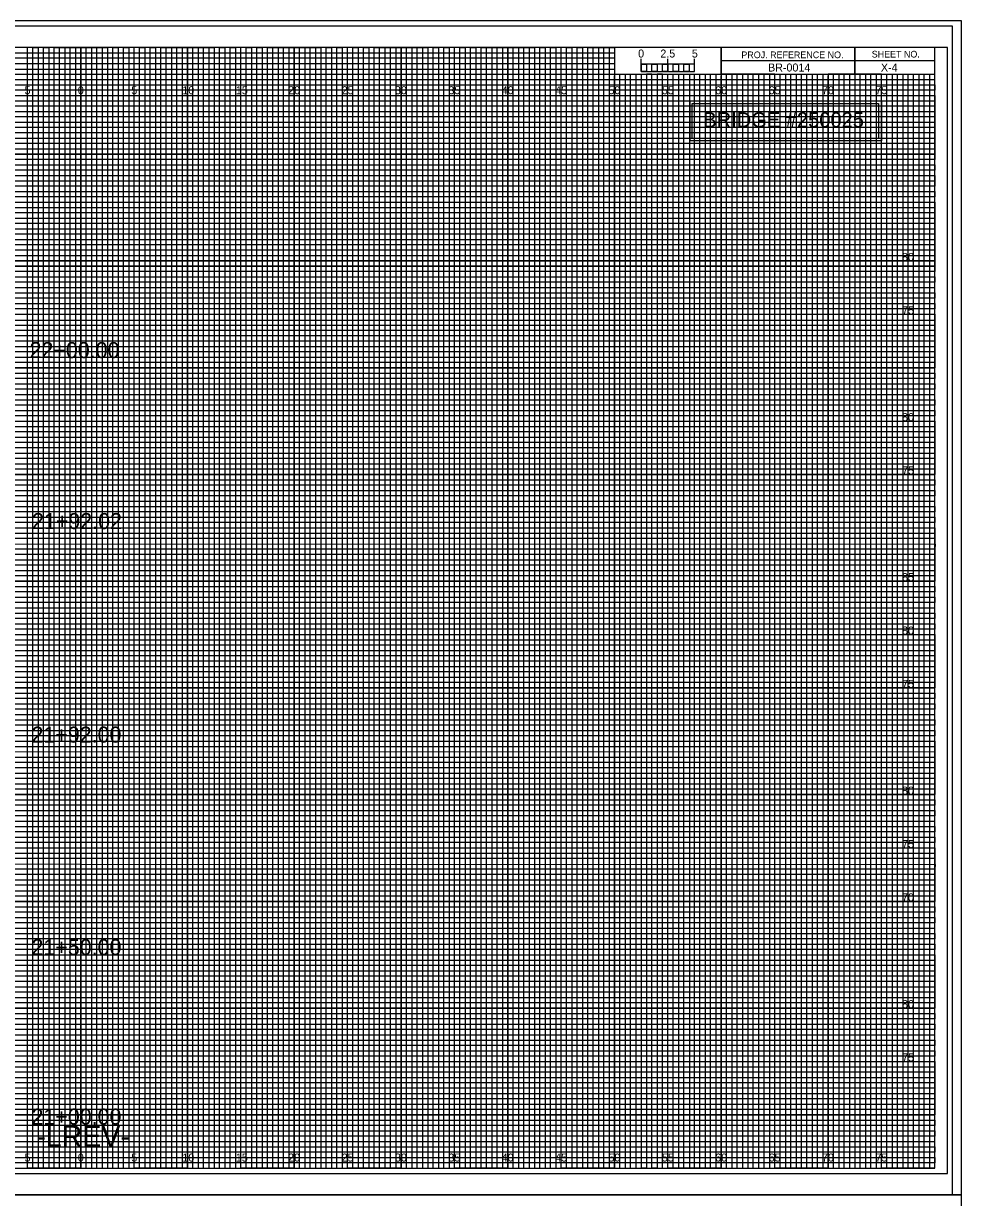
# Model space of a CAD drawing. Extents: x -8 to 533, y -20 to 768.
# Drawn here: x 74.6 to 162.5, y 327.2 to 437.2 of the extents above; entities that cross this region are included whole.
import ezdxf

# ---------------------------------------------------------------- set-up
doc = ezdxf.new("R2010")
doc.units = 0
for name, color, linetype in [('Old_Level_1', 7, 'Continuous'), ('Old_Level_34', 7, 'Continuous'), ('Prop Grid Mask', 7, 'Continuous'), ('Prop XS Alignment Label', 7, 'Continuous'), ('Prop XS Bar Scale Labels', 7, 'Continuous'), ('Prop XS Elevation Labels', 7, 'Continuous'), ('Prop XS Offset Labels', 7, 'Continuous'), ('Prop XS Project Number', 7, 'Continuous'), ('Prop XS Sheet Number', 7, 'Continuous'), ('Prop XS Station Labels', 7, 'Continuous'), ('Sheet Cross Section CELL', 7, 'Continuous'), ('Sheet Cross Section Grid Major CELL', 7, 'Continuous'), ('Sheet Cross Section Grid Middle CELL', 7, 'Continuous'), ('Sheet Cross Section Grid Minor 1 CELL', 7, 'Continuous'), ('Sheet Cross Section Grid Minor 2 CELL', 7, 'Continuous'), ('Sheet Cross Section Scale CELL', 7, 'Continuous'), ('Sheet Cutting Line CELL', 7, 'Continuous'), ('Sheet DOT Grid CELL', 7, 'Continuous'), ('Sheet Plot Border Inside CELL', 7, 'Continuous'), ('Sheet Plot Border Outside CELL', 7, 'Continuous'), ('WEI Plot Border', 7, 'Continuous')]:
    doc.layers.add(name, color=color, linetype=linetype)

msp = doc.modelspace()

# ---------------------------------------------------------------- linework, layer by layer
at = {"layer": 'Old_Level_34'}
msp.add_lwpolyline([(137.26, 429.75), (154.74, 429.75), (154.74, 426.46), (137.26, 426.46)], close=True, dxfattribs=at)
at = {"layer": 'Prop Grid Mask'}
msp.add_lwpolyline([(137.08, 430), (155, 430), (155, 426.24), (137.08, 426.24)], close=True, dxfattribs=at)
at = {"layer": 'Sheet Cross Section CELL'}
for p, q in [((152.5, 435), (152.5, 432.5)), ((152.5, 432.5), (152.5, 435)), ((160, 433.75), (140, 433.75)), ((140, 433.75), (140, 432.5)), ((140, 432.5), (160, 432.5))]:
    msp.add_line(p, q, dxfattribs=at)
for points in [[(160, 435), (0, 435), (0, 330), (160, 330)], [(140, 435), (130, 435), (130, 432.51), (140, 432.51)], [(160, 435), (140, 435), (140, 432.5), (160, 432.5)]]:
    msp.add_lwpolyline(points, close=True, dxfattribs=at)
at = {"layer": 'Sheet Cross Section Grid Major CELL'}
for p, q in [((75, 435), (70, 435)), ((75, 330), (75, 435)), ((85, 435), (80, 435)), ((80, 435), (80, 330)), ((85, 330), (85, 435)), ((95, 435), (90, 435)), ((90, 435), (90, 330)), ((95, 330), (95, 435)), ((105, 435), (100, 435)), ((100, 435), (100, 330)), ((105, 330), (105, 435)), ((115, 435), (110, 435)), ((110, 435), (110, 330)), ((115, 330), (115, 435)), ((125, 435), (120, 435)), ((120, 435), (120, 330)), ((125, 330), (125, 435)), ((130, 435), (130, 330)), ((135, 330), (135, 432.5)), ((145, 432.5), (140, 432.5)), ((140, 432.5), (140, 330)), ((145, 330), (145, 432.5)), ((155, 432.5), (150, 432.5)), ((150, 432.5), (150, 330)), ((155, 330), (155, 432.5)), ((80, 330), (75, 330)), ((90, 330), (85, 330)), ((100, 330), (95, 330)), ((110, 330), (105, 330)), ((120, 330), (115, 330)), ((130, 330), (125, 330)), ((140, 330), (135, 330)), ((150, 330), (145, 330)), ((160, 330), (155, 330)), ((160, 330), (160, 330))]:
    msp.add_line(p, q, dxfattribs=at)
for points in [[(0, 430), (160, 430), (160, 425), (0, 425)], [(0, 420), (160, 420), (160, 415), (0, 415)], [(0, 410), (160, 410), (160, 405), (0, 405)], [(0, 400), (160, 400), (160, 395), (0, 395)], [(0, 390), (160, 390), (160, 385), (0, 385)], [(0, 380), (160, 380), (160, 375), (0, 375)], [(0, 370), (160, 370), (160, 365), (0, 365)], [(0, 360), (160, 360), (160, 355), (0, 355)], [(0, 350), (160, 350), (160, 345), (0, 345)], [(0, 340), (160, 340), (160, 335), (0, 335)]]:
    msp.add_lwpolyline(points, dxfattribs=at)
at = {"layer": 'Sheet Cross Section Grid Middle CELL'}
for points in [[(72.5, 330), (77.5, 330), (77.5, 435), (82.5, 435), (82.5, 330), (87.5, 330), (87.5, 435), (92.5, 435), (92.5, 330), (97.5, 330), (97.5, 435), (102.5, 435), (102.5, 330), (107.5, 330), (107.5, 435), (112.5, 435), (112.5, 330), (117.5, 330), (117.5, 435), (122.5, 435), (122.5, 330), (127.5, 330), (127.5, 435), (129.97, 435), (130, 435), (130, 432.5), (132.5, 432.5), (132.5, 330), (137.5, 330), (137.5, 432.5), (142.5, 432.5), (142.5, 330), (147.5, 330), (147.5, 432.5), (152.5, 432.5), (152.5, 330), (157.5, 330), (157.5, 432.5)], [(0, 432.5), (137.5, 432.5)], [(0, 422.5), (160, 422.5), (160, 427.5), (0, 427.5)], [(0, 412.5), (160, 412.5), (160, 417.5), (0, 417.5)], [(0, 402.5), (160, 402.5), (160, 407.5), (0, 407.5)], [(0, 392.5), (160, 392.5), (160, 397.5), (0, 397.5)], [(0, 382.5), (160, 382.5), (160, 387.5), (0, 387.5)], [(0, 372.5), (160, 372.5), (160, 377.5), (0, 377.5)], [(0, 362.5), (160, 362.5), (160, 367.5), (0, 367.5)], [(0, 352.5), (160, 352.5), (160, 357.5), (0, 357.5)], [(0, 342.5), (160, 342.5), (160, 347.5), (0, 347.5)], [(0, 332.5), (160, 332.5), (160, 337.5), (0, 337.5)]]:
    msp.add_lwpolyline(points, dxfattribs=at)
at = {"layer": 'Sheet Cross Section Grid Minor 1 CELL'}
for p, q in [((0, 434.5), (130, 434.5)), ((130, 433.99), (0, 433.99)), ((0, 433.5), (130, 433.5)), ((130, 434.5), (130, 433.99)), ((130, 433.5), (130, 432.94)), ((130, 432.94), (0, 432.94)), ((0, 432), (160, 432))]:
    msp.add_line(p, q, dxfattribs=at)
for points in [[(0, 431.5), (135, 431.5), (160, 431.5), (160, 431), (0, 431)], [(0, 430.5), (160, 430.5), (160, 429.5), (0, 429.5)], [(0, 429), (160, 429), (160, 428.5), (0, 428.49)], [(0, 428), (160, 428), (160, 427), (0, 427)], [(0, 426.5), (160, 426.5), (160, 426), (0, 426)], [(0, 425.5), (160, 425.5), (160, 424.5), (0, 424.5)], [(0, 424), (160, 424), (160, 423.5), (0, 423.5)], [(0, 423), (160, 423), (160, 422), (0, 422)], [(0, 421.5), (160, 421.5), (160, 421), (0, 421)], [(0, 420.5), (160, 420.5), (160, 419.5), (0, 419.5)], [(0, 419), (160, 419), (160, 418.5), (0, 418.5)], [(0, 418), (160, 418), (160, 416.98), (160, 416.5), (160, 416), (0, 416)], [(0, 417), (160, 417), (160, 416.5), (0, 416.5)], [(0, 415.5), (160, 415.5), (160, 414.5), (0, 414.51)], [(0, 414.51), (160, 414.5), (160, 414), (0, 414)], [(0, 413.5), (160, 413.5), (160, 413), (0, 413)], [(0, 412), (160, 412), (160, 411.5), (0, 411.5)], [(0, 411), (160, 411), (160, 410.5), (0, 410.5)], [(-0.04, 409.44), (160, 409.44), (160, 408.94), (-0.04, 408.94)], [(0, 408.5), (160, 408.5), (160, 408), (0, 408)], [(0, 407), (160, 407), (160, 406.5), (0, 406.5)], [(0, 406), (160, 406), (160, 405.5), (0, 405.5)], [(0, 404.5), (160, 404.5), (160, 404), (0, 404)], [(0, 403.5), (160, 403.5), (160, 403), (0, 403)], [(0, 402), (160, 402), (160, 401.5), (0, 401.5)], [(0, 401), (160, 401), (160, 400.5), (0, 400.5)], [(0, 399.5), (160, 399.5), (160, 398.99), (0, 399)], [(0, 398.5), (160, 398.5), (160, 398), (0, 398)], [(0, 397), (160, 397), (160, 396.5), (0, 396.5)], [(0, 396), (160, 396), (160, 395.5), (0, 395.5)], [(0, 394.5), (160, 394.5), (160, 394), (0, 394)], [(0, 393.5), (160, 393.5), (160, 393), (0, 393)], [(0, 392), (160, 392), (160, 391.5), (0, 391.5)], [(0, 391), (160, 391), (160, 390.5), (0, 390.5)], [(0, 389.5), (160, 389.5), (160, 389), (0, 389)], [(0, 388.5), (160.03, 388.45), (160, 388), (0, 388)], [(0, 387), (160, 387), (160, 386.5), (0, 386.5)], [(0, 386), (160, 386), (160, 385.5), (0, 385.5)], [(0, 384.5), (160, 384.5), (160, 384), (0, 384)], [(0, 383.5), (160, 383.5), (160, 383), (0, 383)], [(0, 382), (160, 382), (160, 381.5), (0, 381.5)], [(0, 381), (160, 381), (160, 380.5), (0, 380.5)], [(0, 379.5), (160, 379.5), (160, 379), (0, 379)], [(0, 378.5), (160, 378.5), (160, 378), (0, 378)], [(0, 377), (160, 377), (160, 376.5), (0, 376.5)], [(0, 376), (160, 376), (160, 375.5), (0, 375.5)], [(0, 374.5), (160, 374.5), (160, 374), (0, 374)], [(0, 373.5), (160, 373.5), (160, 373), (0, 373)], [(0, 372), (160, 372), (160, 371.5), (0, 371.5)], [(0, 371), (160, 371), (160, 370.5), (0, 370.5)], [(0, 369.5), (160, 369.5), (160, 368.99), (0, 369)], [(0, 368.5), (160, 368.5), (160, 368), (0, 368)], [(0, 367), (160, 367), (160, 366.5), (0, 366.5)], [(0, 366), (160, 366), (160, 365.5), (0, 365.5)], [(0, 364.5), (160, 364.5), (160, 364), (0, 364)], [(0, 363.5), (160, 363.5), (160, 363), (0, 363)], [(0, 362), (160, 362), (160, 361.5), (0, 361.5)], [(0, 361), (160, 361), (160, 360.5), (0, 360.5)], [(0, 359.5), (160, 359.5), (160, 359), (0, 359)], [(0, 358.5), (160.03, 358.45), (160, 358), (0, 358)], [(0, 357), (160, 357), (160, 356.5), (0, 356.5)], [(0, 356), (160, 356), (160, 355.5), (0, 355.5)], [(0, 354.5), (160, 354.5), (160, 354), (0, 354)], [(0, 353.5), (160, 353.5), (160, 353), (0, 353)], [(0, 352), (160, 352), (160, 351.5), (0, 351.5)], [(0, 351), (160, 351), (160, 350.5), (0, 350.5)], [(0, 349.5), (160, 349.5), (160, 349), (0, 349)], [(0, 348.5), (160, 348.5), (160, 348), (0, 348)], [(0, 347), (160, 347), (160, 346.5), (0, 346.5)], [(0, 346), (160, 346), (160, 345.5), (0, 345.5)], [(0, 344.5), (160, 344.5), (160, 344), (0, 344)], [(0, 343.5), (160, 343.5), (160, 343), (0, 343)], [(0, 342), (160, 342), (160, 341.5), (0, 341.5)], [(0, 341), (160, 341), (160, 340.5), (0, 340.5)], [(0, 339.5), (160, 339.5), (160, 339), (0, 339)], [(0, 338.5), (160, 338.5), (160, 338), (0, 338)], [(0, 337), (160, 337), (160, 336.5), (0, 336.5)], [(0, 336), (160, 336), (160, 335.5), (0, 335.5)], [(0, 334.5), (160, 334.5), (160, 334), (0, 334)], [(0, 333.5), (160, 333.5), (160, 333), (0, 333)], [(0, 332), (160, 332), (160, 331.5), (0, 331.5)], [(0, 331), (160, 331), (160, 330.5), (0, 330.5)]]:
    msp.add_lwpolyline(points, dxfattribs=at)
at = {"layer": 'Sheet Cross Section Grid Minor 2 CELL'}
for p, q in [((133.5, 432.5), (133, 432.5)), ((133, 432.5), (133, 330)), ((133.5, 330), (133.5, 432.5)), ((134.5, 432.5), (134, 432.5)), ((134, 432.5), (134, 330)), ((134.5, 330), (134.5, 432.5)), ((133, 330), (132.5, 330)), ((134, 330), (133.5, 330))]:
    msp.add_line(p, q, dxfattribs=at)
for points in [[(75, 330), (75.5, 330), (75.5, 435), (76, 435), (76, 330)], [(76, 330), (76.5, 330), (76.5, 435), (77, 435), (77, 330)], [(77.5, 330), (78, 330), (78, 435), (78.5, 435), (78.5, 330)], [(78.5, 330), (79, 330), (79, 435), (79.5, 435), (79.5, 330)], [(80, 330), (80.5, 330), (80.5, 435), (81, 435), (81, 330)], [(81, 330), (81.5, 330), (81.5, 435), (82, 435), (82, 330)], [(82.5, 330), (83, 330), (83, 435), (83.5, 435), (83.5, 330)], [(83.5, 330), (84, 330), (84, 435), (84.5, 435), (84.5, 330)], [(85, 330), (85.5, 330), (85.5, 435), (86, 435), (86, 330)], [(86, 330), (86.5, 330), (86.5, 435), (87, 435), (87, 330)], [(87.5, 330), (88, 330), (88, 435), (88.5, 435), (88.5, 330)], [(88.5, 330), (89, 330), (89, 435), (89.5, 435), (89.5, 330)], [(90, 330), (90.5, 330), (90.5, 435), (91, 435), (91, 330)], [(91, 330), (91.5, 330), (91.5, 435), (92, 435), (92, 330)], [(92.5, 330), (93, 330), (93, 435), (93.5, 435), (93.5, 330)], [(93.5, 330), (94, 330), (94, 435), (94.5, 435), (94.5, 330)], [(95, 330), (95.5, 330), (95.5, 435), (96, 435), (96, 330)], [(96, 330), (96.5, 330), (96.5, 435), (97, 435), (97, 330)], [(97.5, 330), (98, 330), (98, 435), (98.5, 435), (98.5, 330)], [(98.5, 330), (99, 330), (99, 435), (99.5, 435), (99.5, 330)], [(100, 330), (100.5, 330), (100.5, 435), (101, 435), (101, 330)], [(101, 330), (101.5, 330), (101.5, 435), (102, 435), (102, 330)], [(102.5, 330), (103, 330), (103, 435), (103.5, 435), (103.5, 330)], [(103.5, 330), (104, 330), (104, 435), (104.5, 435), (104.5, 330)], [(105, 330), (105.5, 330), (105.5, 435), (106, 435), (106, 330)], [(106, 330), (106.5, 330), (106.5, 435), (107, 435), (107, 330)], [(107.5, 330), (108, 330), (108, 435), (108.5, 435), (108.5, 330)], [(108.5, 330), (109, 330), (109, 435), (109.5, 435), (109.5, 330)], [(110, 330), (110.5, 330), (110.5, 435), (111, 435), (111, 330)], [(111, 330), (111.5, 330), (111.5, 435), (112, 435), (112, 330)], [(112.5, 330), (113, 330), (113, 435), (113.5, 435), (113.5, 330)], [(113.5, 330), (114, 330), (114, 435), (114.5, 435), (114.5, 330)], [(115, 330), (115.5, 330), (115.5, 435), (116, 435), (116, 330)], [(116, 330), (116.5, 330), (116.5, 435), (117, 435), (117, 330)], [(117.5, 330), (118, 330), (118, 435), (118.5, 435), (118.5, 330)], [(118.5, 330), (119, 330), (119, 435), (119.5, 435), (119.5, 330)], [(120, 330), (120.5, 330), (120.5, 435), (121, 435), (121, 330)], [(121, 330), (121.5, 330), (121.5, 435), (122, 435), (122, 330)], [(122.5, 330), (123, 330), (123, 435), (123.5, 435), (123.5, 330)], [(123.5, 330), (124, 330), (124, 435), (124.5, 435), (124.5, 330)], [(125, 330), (125.5, 330), (125.5, 435), (126, 435), (126, 330)], [(126, 330), (126.5, 330), (126.5, 435), (127, 435), (127, 330)], [(127.5, 330), (128, 330), (128, 435), (128.5, 435), (128.5, 330)], [(128.5, 330), (129, 330), (129, 435), (129.5, 435), (129.5, 330)], [(130, 330), (130.5, 330), (130.5, 432.5), (131.01, 432.5), (131.01, 330)], [(131, 330), (131.5, 330), (131.5, 432.5), (132, 432.5), (132, 330)], [(135, 330), (135.49, 330), (135.49, 432.5), (136, 432.5), (136, 330)], [(136, 330), (136.5, 330), (136.5, 432.5), (137.03, 432.5), (137.03, 330)], [(137.5, 330), (138, 330), (138, 432.5), (138.5, 432.5), (138.5, 330)], [(138.5, 330), (139, 330), (139, 432.5), (139.5, 432.5), (139.5, 330)], [(140, 330), (140.5, 330), (140.5, 432.5), (141, 432.5), (141, 330)], [(141, 330), (141.5, 330), (141.5, 432.5), (142, 432.5), (142, 330)], [(142.5, 330), (143, 330), (143, 432.5), (143.5, 432.5), (143.5, 330)], [(143.5, 330), (144, 330), (144, 432.5), (144.5, 432.5), (144.5, 330)], [(145, 330), (145.5, 330), (145.5, 432.5), (146, 432.5), (146, 330)], [(146, 330), (146.5, 330), (146.5, 432.5), (147, 432.5), (147, 330)], [(147.5, 330), (148, 330), (148, 432.5), (148.5, 432.5), (148.5, 330)], [(148.5, 330), (149, 330), (149, 432.5), (149.5, 432.5), (149.5, 330)], [(150, 330), (150.5, 330), (150.5, 432.5), (151, 432.5), (151, 330)], [(151, 330), (151.5, 330), (151.5, 432.5), (152, 432.5), (152, 330)], [(152.5, 330), (153, 330), (153, 432.5), (153.5, 432.5), (153.5, 330)], [(153.5, 330), (154, 330), (154, 432.5), (154.5, 432.5), (154.5, 330)], [(155, 330), (155.5, 330), (155.5, 432.5), (156, 432.5), (156, 330)], [(156, 330), (156.5, 330), (156.5, 432.5), (157, 432.5), (157, 330)], [(157.5, 330), (158, 330), (158, 432.5), (158.5, 432.5), (158.5, 330)], [(158.5, 330), (159, 330), (159, 432.5), (159.5, 432.5), (159.5, 330)]]:
    msp.add_lwpolyline(points, dxfattribs=at)
at = {"layer": 'Sheet Cross Section Scale CELL'}
for p, q in [((132.5, 432.75), (132.5, 433.95)), ((132.5, 433.45), (132.5, 433.95)), ((135, 432.75), (135, 433.95)), ((137.5, 432.75), (137.5, 433.95)), ((137.5, 433.45), (137.5, 433.95))]:
    msp.add_line(p, q, dxfattribs=at)
for points in [[(137.5, 433.45), (132.5, 433.45), (132.5, 432.75), (137.5, 432.75)], [(132.5, 433.45), (133, 433.45), (133, 432.75), (132.5, 432.75)], [(133.5, 433.45), (134, 433.45), (134, 432.75), (133.5, 432.75)], [(134.5, 433.45), (135, 433.45), (135, 432.75), (134.5, 432.75)], [(135.5, 433.45), (136, 433.45), (136, 432.75), (135.5, 432.75)], [(136.5, 433.45), (137, 433.45), (137, 432.75), (136.5, 432.75)]]:
    msp.add_lwpolyline(points, close=True, dxfattribs=at)
at = {"layer": 'Sheet Cutting Line CELL'}
for p, q in [((161.65, 437), (-6.7, 437)), ((-6.7, 327.5), (161.65, 327.5))]:
    msp.add_line(p, q, dxfattribs=at)
at = {"layer": 'Sheet DOT Grid CELL'}
for p, q in [((75, 330), (75, 435)), ((80, 330), (80, 435)), ((85, 330), (85, 435)), ((90, 330), (90, 435)), ((95, 330), (95, 435)), ((100, 330), (100, 435)), ((105, 330), (105, 435)), ((110, 330), (110, 435)), ((115, 330), (115, 435)), ((120, 330), (120, 435)), ((125, 330), (125, 435)), ((130, 330), (130, 432.34)), ((135, 330), (135, 432.34)), ((140, 330), (140, 432.34)), ((145, 330), (145, 432.34)), ((150, 330), (150, 432.34)), ((155, 330), (155, 432.34)), ((0, 430), (160, 430)), ((0, 425), (160, 425)), ((0, 420), (160, 420)), ((0, 415), (160, 415)), ((0, 410), (160, 410)), ((0, 405), (160, 405)), ((0, 400), (160, 400)), ((0, 395), (160, 395)), ((0, 390), (160, 390)), ((0, 385), (160, 385)), ((0, 380), (160, 380)), ((0, 375), (160, 375)), ((0, 370), (160, 370)), ((0, 365), (160, 365)), ((0, 360), (160, 360)), ((0, 355), (160, 355)), ((0, 350), (160, 350)), ((0, 345), (160, 345)), ((0, 340), (160, 340)), ((0, 335), (160, 335))]:
    msp.add_line(p, q, dxfattribs=at)
at = {"layer": 'Sheet Plot Border Inside CELL'}
msp.add_lwpolyline([(-5.4, 329.5), (161.2, 329.5), (161.2, 435), (-5.4, 435)], close=True, dxfattribs=at)
at = {"layer": 'Sheet Plot Border Outside CELL'}
msp.add_lwpolyline([(-6.7, 327.5), (161.65, 327.5), (161.65, 437), (-6.7, 437)], close=True, dxfattribs=at)
at = {"layer": 'WEI Plot Border'}
for points in [[(-7.5, 327.5), (162.5, 327.5), (162.5, 437.5), (-7.5, 437.5)], [(-7.5, 217.5), (162.5, 217.5), (162.5, 327.5), (-7.5, 327.5)]]:
    msp.add_lwpolyline(points, close=True, dxfattribs=at)

# ---------------------------------------------------------------- texts
at = {"layer": 'Old_Level_1'}
msp.add_text('BRIDGE #250025', height=1.4062, rotation=360, dxfattribs=at).set_placement((138.31, 427.52))
at = {"layer": 'Prop XS Alignment Label'}
msp.add_text('-LREV-', height=2, dxfattribs=at).set_placement((75.84, 332))
at = {"layer": 'Prop XS Bar Scale Labels'}
for s, p in [('2.5', (134.29, 434.06)), ('5', (137.24, 434.06))]:
    msp.add_text(s, height=0.75, dxfattribs=at).set_placement(p)
at = {"layer": 'Prop XS Elevation Labels'}
for s, p in [('80', (156.93, 415)), ('75', (156.94, 410)), ('80', (156.93, 400)), ('75', (156.94, 395)), ('85', (156.94, 385)), ('80', (156.93, 380)), ('75', (156.94, 375)), ('80', (156.93, 365)), ('75', (156.94, 360)), ('70', (156.93, 355)), ('80', (156.93, 345)), ('75', (156.94, 340))]:
    msp.add_text(s, height=0.75, dxfattribs=at).set_placement(p)
at = {"layer": 'Prop XS Offset Labels'}
for s, p in [('5', (74.74, 430.62)), ('0', (79.73, 430.62)), ('0', (79.73, 430.62)), ('5', (84.74, 430.62)), ('10', (89.52, 430.62)), ('15', (94.53, 430.62)), ('20', (99.43, 430.62)), ('25', (104.44, 430.62)), ('30', (109.43, 430.62)), ('35', (114.44, 430.62)), ('40', (119.43, 430.62)), ('45', (124.44, 430.62)), ('50', (129.43, 430.62)), ('55', (134.44, 430.62)), ('60', (139.43, 430.62)), ('65', (144.44, 430.62)), ('70', (149.43, 430.62)), ('75', (154.44, 430.62)), ('5', (74.74, 330.62)), ('0', (79.73, 330.62)), ('0', (79.73, 330.62)), ('5', (84.74, 330.62)), ('10', (89.52, 330.62)), ('15', (94.53, 330.62)), ('20', (99.43, 330.62)), ('25', (104.44, 330.62)), ('30', (109.43, 330.62)), ('35', (114.44, 330.62)), ('40', (119.43, 330.62)), ('45', (124.44, 330.62)), ('50', (129.43, 330.62)), ('55', (134.44, 330.62)), ('60', (139.43, 330.62)), ('65', (144.44, 330.62)), ('70', (149.43, 330.62)), ('75', (154.44, 330.62))]:
    msp.add_text(s, height=0.75, dxfattribs=at).set_placement(p)
at = {"layer": 'Prop XS Project Number'}
msp.add_text('BR-0014', height=0.75, dxfattribs=at).set_placement((144.38, 432.75))
at = {"layer": 'Prop XS Sheet Number'}
msp.add_text('X-4', height=0.75, dxfattribs=at).set_placement((154.95, 432.75))
at = {"layer": 'Prop XS Station Labels'}
for s, p in [('22+00.00', (75.21, 405.9)), ('21+92.02', (75.44, 389.88)), ('21+92.00', (75.39, 369.87)), ('21+50.00', (75.39, 349.96)), ('21+00.00', (75.39, 334.08))]:
    msp.add_text(s, height=1.5, dxfattribs=at).set_placement(p)
at = {"layer": 'Sheet Cross Section CELL'}
for s, p in [('PROJ. REFERENCE NO.', (141.88, 434)), ('SHEET NO.', (154.09, 434.06))]:
    msp.add_text(s, height=0.625, dxfattribs=at).set_placement(p)
at = {"layer": 'Sheet Cross Section Scale CELL'}
msp.add_text('0', height=0.75, dxfattribs=at).set_placement((132.21, 434.06))

doc.saveas('drawing.dxf')
